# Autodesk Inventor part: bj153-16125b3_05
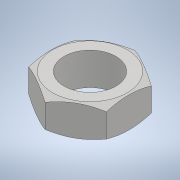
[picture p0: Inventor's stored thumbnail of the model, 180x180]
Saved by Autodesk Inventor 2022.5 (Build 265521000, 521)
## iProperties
Part Number: bj153-16125b3_05
Material: 一般
Document SubType Name: Modeling
Designer: ImaoCorp
Density: 1 g/cm^3
Appearance: 既定
Author: ImaoCorp
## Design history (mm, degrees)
feature "bj153-16125b3_05"
node "ソリッド1"
